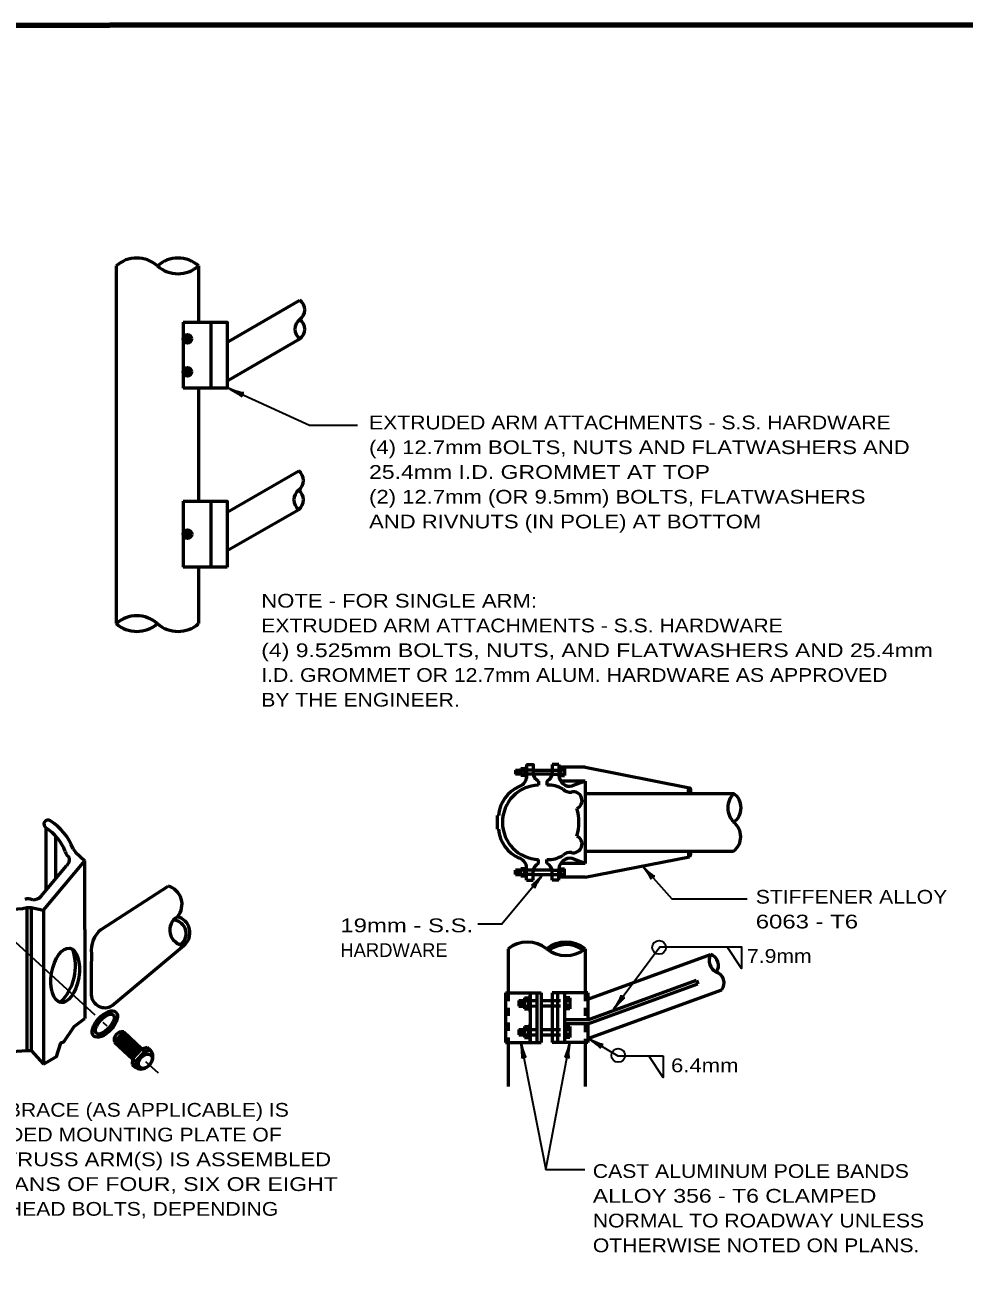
# Model space of a CAD drawing. Extents: x -20 to 693, y -19 to 435.
# Drawn here: x 342.4 to 513.2, y 202.7 to 429.4 of the extents above; entities that cross this region are included whole.
import ezdxf

# ---------------------------------------------------------------- set-up
doc = ezdxf.new("R2010")
doc.units = 0
doc.linetypes.add('SHORT_DASHED', pattern=[2.7, 1.5, -1.2])
doc.layers.add('1', color=7, linetype='Continuous', lineweight=53)

msp = doc.modelspace()

# ---------------------------------------------------------------- hatches: boundary and pattern name
at = {"layer": '1'}
for points in [[(372.737, 372.31, 1), (371.205, 372.31, 1)], [(372.737, 366.308, 1), (371.205, 366.308, 1)], [(372.741, 336.811, 1), (371.209, 336.811, 1)]]:
    msp.add_hatch(color=256, dxfattribs=at).paths.add_polyline_path(points)

# ---------------------------------------------------------------- linework, layer by layer
for p, q in [((359.012, 385.571), (359.012, 320.571)), ((374.012, 385.571), (374.012, 375.321)), ((379.415, 371.823), (392.406, 379.323)), ((371.216, 375.321), (371.216, 363.321)), ((376.216, 375.321), (376.216, 363.321)), ((379.415, 364.823), (392.406, 372.323)), ((374.012, 363.321), (374.012, 342.821)), ((379.216, 340.821), (392.206, 348.321)), ((371.216, 342.821), (371.216, 330.821)), ((376.216, 342.821), (376.216, 330.821)), ((379.216, 333.821), (392.206, 341.321)), ((379.216, 330.821), (371.216, 330.821)), ((374.012, 330.821), (374.012, 320.571)), ((433.609, 294.959), (433.609, 292.459)), ((439.532, 294.959), (438.282, 294.959)), ((438.282, 294.959), (438.282, 293.459)), ((439.532, 294.959), (439.532, 292.959)), ((431.597, 293.959), (431.597, 293.209)), ((431.597, 293.959), (433.347, 293.959)), ((433.347, 293.209), (431.597, 293.209)), ((431.847, 293.834), (431.847, 293.334)), ((432.097, 293.709), (432.097, 293.459)), ((432.347, 293.834), (432.347, 293.334)), ((432.597, 294.209), (432.597, 292.959)), ((432.597, 294.209), (433.347, 294.209)), ((433.347, 292.959), (432.597, 292.959)), ((433.347, 294.334), (433.597, 294.334)), ((433.347, 294.334), (433.347, 292.834)), ((433.597, 292.834), (433.347, 292.834)), ((434.859, 293.959), (438.282, 293.959)), ((438.271, 293.209), (434.859, 293.209)), ((444.282, 294.459), (439.532, 294.459)), ((439.782, 294.334), (439.532, 294.334)), ((439.532, 292.834), (439.782, 292.834)), ((439.782, 294.334), (439.782, 292.834)), ((440.532, 294.209), (439.782, 294.209)), ((440.532, 293.959), (439.782, 293.959)), ((439.782, 293.209), (440.532, 293.209)), ((439.782, 292.959), (440.532, 292.959)), ((440.532, 294.209), (440.532, 292.959)), ((444.282, 294.459), (463.282, 290.709)), ((435.833, 291.959), (435.833, 291.209)), ((437.308, 291.959), (437.308, 291.209)), ((444.282, 291.959), (439.808, 291.959)), ((444.282, 291.959), (441.948, 291.063)), ((444.282, 291.959), (444.282, 276.959)), ((444.282, 289.709), (471.375, 289.709)), ((428.282, 285.709), (428.282, 283.209)), ((428.282, 285.709), (428.532, 285.709)), ((346.245, 283.45), (346.245, 272.035)), ((347.995, 281.992), (347.995, 274.135)), ((428.282, 283.209), (428.532, 283.209)), ((444.282, 279.209), (471.282, 279.209)), ((345.391, 271.009), (350.01, 276.552)), ((345.786, 268.483), (353.286, 277.483)), ((353.286, 264.983), (353.286, 277.483)), ((435.833, 276.959), (435.833, 277.709)), ((437.308, 276.959), (437.308, 277.709)), ((444.282, 276.959), (439.808, 276.959)), ((444.282, 276.959), (441.948, 277.855)), ((444.282, 274.459), (463.282, 278.209)), ((431.597, 274.995), (431.597, 275.745)), ((433.347, 275.745), (431.597, 275.745)), ((431.597, 274.995), (433.347, 274.995)), ((431.847, 275.12), (431.847, 275.62)), ((432.097, 275.245), (432.097, 275.495)), ((432.347, 275.12), (432.347, 275.62)), ((432.597, 274.745), (432.597, 275.995)), ((433.347, 275.995), (432.597, 275.995)), ((432.597, 274.745), (433.347, 274.745)), ((433.597, 276.12), (433.347, 276.12)), ((433.347, 274.62), (433.347, 276.12)), ((433.347, 274.62), (433.597, 274.62)), ((433.609, 273.959), (433.609, 276.459)), ((438.271, 275.745), (434.859, 275.745)), ((434.859, 273.959), (434.859, 275.459)), ((434.859, 274.995), (438.282, 274.995)), ((438.282, 273.959), (438.282, 275.459)), ((439.532, 276.12), (439.782, 276.12)), ((439.532, 273.959), (439.532, 275.959)), ((439.782, 274.62), (439.532, 274.62)), ((444.282, 274.459), (439.532, 274.459)), ((439.782, 274.62), (439.782, 276.12)), ((439.782, 275.995), (440.532, 275.995)), ((439.782, 275.745), (440.532, 275.745)), ((440.532, 274.995), (439.782, 274.995)), ((440.532, 274.745), (439.782, 274.745)), ((440.532, 274.745), (440.532, 275.995)), ((356.286, 264.983), (368.447, 272.88)), ((433.609, 273.959), (434.859, 273.959)), ((439.532, 273.959), (438.282, 273.959)), ((342.786, 268.983), (342.786, 242.983)), ((343.536, 268.983), (343.536, 242.983)), ((345.786, 268.483), (345.786, 240.483)), ((358.286, 251.154), (371.309, 262.081)), ((430.282, 261.459), (430.282, 253.459)), ((444.282, 261.459), (444.282, 253.459)), ((444.782, 252.308), (467.077, 260.423)), ((444.782, 248.584), (464.516, 255.766)), ((444.782, 247.834), (464.757, 255.104)), ((444.782, 245.173), (469.13, 254.035)), ((464.516, 255.766), (464.757, 255.104)), ((429.782, 253.459), (436.282, 253.459)), ((429.782, 253.459), (429.782, 244.459)), ((432.256, 252.073), (434.006, 252.073)), ((432.256, 252.073), (432.256, 251.073)), ((432.506, 251.948), (432.506, 251.198)), ((432.756, 251.823), (432.756, 251.323)), ((433.006, 251.948), (433.006, 251.198)), ((433.256, 252.573), (433.256, 250.573)), ((433.256, 252.573), (434.006, 252.573)), ((434.006, 252.823), (434.006, 250.323)), ((434.006, 252.823), (434.256, 252.823)), ((434.282, 253.459), (434.282, 244.459)), ((435.532, 253.459), (435.532, 244.459)), ((436.282, 253.459), (436.282, 244.459)), ((436.282, 252.077), (438.282, 252.08)), ((444.782, 253.459), (438.282, 253.459)), ((438.282, 253.459), (438.282, 244.459)), ((439.282, 253.459), (439.282, 244.459)), ((440.532, 253.459), (440.532, 244.459)), ((440.782, 252.834), (440.532, 252.834)), ((440.782, 252.834), (440.782, 250.334)), ((441.532, 252.584), (440.782, 252.584)), ((441.532, 252.084), (440.782, 252.084)), ((441.532, 252.584), (441.532, 250.584)), ((444.782, 253.459), (444.782, 248.584)), ((432.256, 251.073), (434.006, 251.073)), ((433.256, 250.573), (434.006, 250.573)), ((434.006, 250.323), (434.256, 250.323)), ((436.282, 251.077), (438.282, 251.08)), ((440.782, 250.334), (440.532, 250.334)), ((441.532, 251.084), (440.782, 251.084)), ((441.532, 250.584), (440.782, 250.584)), ((433.256, 247.323), (433.256, 245.323)), ((433.256, 247.323), (434.006, 247.323)), ((434.006, 247.573), (434.006, 245.073)), ((434.006, 247.573), (434.256, 247.573)), ((444.782, 248.584), (440.532, 248.584)), ((444.782, 247.834), (440.532, 247.834)), ((440.782, 247.584), (440.532, 247.584)), ((440.782, 247.584), (440.782, 245.084)), ((441.532, 247.334), (440.782, 247.334)), ((441.532, 247.334), (441.532, 245.334)), ((444.782, 247.834), (444.782, 244.459)), ((358.687, 244.509), (360.376, 246.352)), ((359.055, 244.171), (360.744, 246.014)), ((359.424, 243.833), (361.113, 245.677)), ((359.793, 243.496), (361.482, 245.339)), ((360.161, 243.158), (361.85, 245.001)), ((360.376, 246.352), (363.693, 243.312)), ((432.256, 246.823), (434.006, 246.823)), ((432.256, 246.823), (432.256, 245.823)), ((432.256, 245.823), (434.006, 245.823)), ((432.506, 246.698), (432.506, 245.948)), ((432.756, 246.573), (432.756, 246.073)), ((433.006, 246.698), (433.006, 245.948)), ((433.256, 245.323), (434.006, 245.323)), ((434.006, 245.073), (434.256, 245.073)), ((436.282, 246.827), (438.282, 246.83)), ((436.282, 245.827), (438.282, 245.83)), ((440.782, 245.084), (440.532, 245.084)), ((441.532, 246.834), (440.782, 246.834)), ((441.532, 245.834), (440.782, 245.834)), ((441.532, 245.334), (440.782, 245.334)), ((358.687, 244.509), (362.005, 241.469)), ((360.53, 242.82), (362.219, 244.663)), ((360.899, 242.482), (362.587, 244.326)), ((361.267, 242.144), (362.956, 243.988)), ((361.636, 241.807), (363.325, 243.65)), ((362.005, 241.469), (363.693, 243.312)), ((362.558, 240.962), (364.246, 242.805)), ((363.693, 243.312), (364.65, 243.605)), ((363.693, 243.312), (364.246, 242.805)), ((364.246, 242.805), (365.203, 243.098)), ((364.65, 243.605), (365.203, 243.098)), ((429.782, 244.459), (436.282, 244.459)), ((430.282, 244.459), (430.282, 236.459)), ((444.782, 244.459), (438.282, 244.459)), ((444.282, 244.459), (444.282, 236.459)), ((362.005, 241.469), (361.917, 240.473)), ((361.917, 240.473), (362.47, 239.966)), ((362.005, 241.469), (362.558, 240.962)), ((362.558, 240.962), (362.47, 239.966))]:
    msp.add_line(p, q, dxfattribs=at)
at = {"layer": '1', "linetype": 'SHORT_DASHED'}
for p, q in [((434.859, 293.959), (433.609, 293.959)), ((434.859, 293.209), (433.609, 293.209)), ((438.271, 293.209), (439.532, 293.209)), ((438.282, 293.959), (439.532, 293.959)), ((434.859, 275.745), (433.609, 275.745)), ((434.859, 274.995), (433.609, 274.995)), ((438.271, 275.745), (439.532, 275.745)), ((438.282, 274.995), (439.532, 274.995)), ((430.282, 253.459), (430.282, 244.459)), ((434.282, 252.074), (436.282, 252.077)), ((438.282, 252.08), (440.532, 252.083)), ((444.282, 253.459), (444.282, 248.584)), ((434.282, 251.074), (436.282, 251.077)), ((438.282, 251.08), (440.532, 251.083)), ((444.282, 247.834), (444.282, 244.459)), ((434.282, 246.824), (436.282, 246.827)), ((434.282, 245.824), (436.282, 245.827)), ((438.282, 246.83), (440.532, 246.833)), ((438.282, 245.83), (440.532, 245.833))]:
    msp.add_line(p, q, dxfattribs=at)
at = {"layer": '1', "lineweight": 13}
for p, q in [((463.282, 289.709), (463.282, 290.709)), ((463.282, 279.209), (463.282, 278.209))]:
    msp.add_line(p, q, dxfattribs=at)
at = {"layer": '1', "lineweight": 35}
for p, q in [((338.443, 264.755), (355.108, 249.484)), ((356.582, 248.133), (357.32, 247.457)), ((364.36, 241.006), (366.65, 238.908)), ((437.152, 221.37), (444.256, 221.37))]:
    msp.add_line(p, q, dxfattribs=at)
at = {"layer": '1', "lineweight": 158}
msp.add_lwpolyline([(687.723, 429.353), (27.973, 429.27), (28.056, -9.063)], dxfattribs=at)
at = {"layer": '1'}
for points in [[(371.216, 375.321), (379.216, 375.321), (379.216, 363.321), (371.216, 363.321)], [(371.216, 342.821), (379.216, 342.821), (379.216, 330.821)], [(433.609, 294.959), (434.859, 294.959), (434.859, 293.459)], [(351.165, 279.662), (351.592, 279.046), (353.286, 277.483)], [(342.786, 268.983), (343.536, 268.983), (345.786, 268.483)], [(353.286, 264.983), (353.286, 251.154), (353.286, 248.82)], [(345.786, 240.483), (348.176, 241.896), (348.953, 244.363), (349.516, 244.551), (351.366, 247.34), (353.286, 248.82)], [(336.286, 243.483), (338.15, 243.747), (340.026, 242.808), (342.786, 242.983)], [(342.786, 242.983), (343.536, 242.983), (345.786, 240.483)]]:
    msp.add_lwpolyline(points, dxfattribs=at)
at = {"layer": '1', "lineweight": 35}
for points in [[(379.455, 363.321), (394.175, 356.611), (402.898, 356.611)], [(454.713, 276.517), (460.039, 270.524), (473.766, 270.524)], [(436.645, 274.995), (429.131, 265.931), (424.763, 265.931)], [(449.458, 250.485), (457.844, 261.828), (472.693, 261.828), (472.693, 257.907), (470.118, 261.828)], [(444.861, 245.202), (450.225, 242.007), (458.457, 242.007)], [(432.615, 244.459), (437.152, 221.37), (441.492, 244.459)], [(458.457, 242.007), (458.457, 238.086), (455.881, 242.007)]]:
    msp.add_lwpolyline(points, dxfattribs=at)
at = {"layer": '1'}
for centre in [(371.971, 372.31), (371.971, 366.308), (371.975, 336.811)]:
    msp.add_circle(centre, 0.766, dxfattribs=at)
at = {"layer": '1', "lineweight": 35}
for centre in [(457.732, 261.716), (450.318, 242.101)]:
    msp.add_circle(centre, 1.25, dxfattribs=at)
at = {"layer": '1'}
for centre, radius, start, end in [((362.762, 381.362), 5.637, 48.29895, 131.70105), ((370.262, 381.362), 5.637, 48.29895, 131.70105), ((370.262, 389.779), 5.637, 228.29895, 311.70105), ((391.116, 377.573), 2.174, 306.3891, 53.6109), ((393.685, 374.073), 2.174, 126.3891, 233.6109), ((391.116, 374.073), 2.174, 306.3891, 53.6109), ((390.916, 346.571), 2.174, 306.3891, 53.6109), ((393.485, 343.071), 2.174, 126.3891, 233.6109), ((390.916, 343.071), 2.174, 306.3891, 53.6109), ((362.762, 316.363), 5.637, 48.29895, 131.70105), ((362.762, 324.78), 5.637, 228.29895, 311.70105), ((370.262, 324.78), 5.637, 228.29895, 311.70105), ((431.589, 292.908), 2.069, 289.57732, 347.45502), ((436.415, 293.403), 1.557, 177.95818, 248.04926), ((436.726, 293.403), 1.557, 291.95074, 2.04182), ((441.484, 292.959), 1.952, 180.00917, 283.74588), ((434.754, 285.229), 6.24, 113.33464, 175.59), ((435.999, 284.459), 6.752, 91.40761, 268.59239), ((437.643, 286.266), 4.954, 57.81212, 93.88207), ((441.541, 291.736), 1.794, 225.41014, 277.71996), ((442.139, 288.411), 1.588, 293.87794, 102.99195), ((473.788, 287.084), 3.566, 132.59281, 227.40719), ((469.441, 287.084), 3.207, 305.05336, 54.94663), ((434.722, 284.459), 8.439, 342.76732, 17.23267), ((341.55, 276.036), 8.775, 20.66388, 57.65371), ((341.55, 276.036), 10.275, 20.66388, 57.65371), ((469.286, 281.834), 3.298, 307.2562, 52.7438), ((434.754, 283.688), 6.24, 184.41, 246.66536), ((442.139, 280.506), 1.588, 257.00805, 66.12206), ((351.362, 279.499), 1.642, 192.85463, 230.60442), ((441.541, 277.181), 1.794, 82.28004, 134.58986), ((348.39, 278.041), 2.201, 317.4286, 347.16534), ((349.7, 277.66), 0.842, 352.66912, 42.58165), ((431.589, 276.009), 2.069, 12.54498, 70.42267), ((436.415, 275.514), 1.557, 111.95074, 182.04182), ((437.643, 282.651), 4.954, 266.11793, 302.18787), ((436.726, 275.514), 1.557, 357.95818, 68.04926), ((441.484, 275.958), 1.952, 76.25412, 179.99082), ((367.528, 269.545), 3.459, 319.44782, 74.5999), ((343.033, 268.914), 1.642, 62.80268, 111.90546), ((343.851, 272.557), 2.183, 268.23866, 314.85412), ((340.283, 278.949), 10.275, 247.10638, 284.09621), ((371.561, 264.872), 2.802, 120.08888, 264.83066), ((369.24, 264.241), 2.482, 304.09123, 82.55014), ((369.451, 264.406), 2.975, 308.63104, 76.2885), ((359.282, 261.238), 4.796, 128.66194, 187.87931), ((342.384, 258.325), 9.229, 314.33212, 19.09649), ((433.782, 257.098), 5.591, 51.2455, 128.7545), ((440.782, 257.098), 5.591, 51.2455, 128.7545), ((440.782, 265.819), 5.591, 231.2455, 308.7545), ((440.847, 257.04), 5.191, 53.42334, 127.51258), ((473.137, 256.082), 118.691, 177.82775, 181.44113), ((469.296, 259.374), 2.454, 154.68436, 240.93436), ((466.528, 258.485), 2.015, 321.44112, 74.17759), ((467.554, 255.291), 2.015, 321.44112, 74.17759), ((356.955, 253.242), 2.476, 183.35172, 302.5103), ((360.104, 244.906), 1.472, 79.351, 195.65274), ((363.782, 241.82), 1.911, 319.45702, 41.96074), ((363.516, 241.335), 1.722, 232.63043, 305.57785)]:
    msp.add_arc(centre, radius, start, end, dxfattribs=at)
at = {"layer": '1', "lineweight": 40}
for centre, major_axis, ratio, start_param, end_param in [((380.387, 362.664), (1.525, -0.888), 0.07063, 6.2823074, 8.5597026), ((380.387, 362.664), (1.525, -0.888), 0.07063, 6.2823074, 8.5597026), ((380.563, 363.12), (-1.69, 0.599), 0.122415, 0.8963533, 3.1415927), ((380.563, 363.12), (-1.69, 0.599), 0.122415, 0.8963533, 3.1415927), ((455.3, 275.539), (-1.035, 1.43), 0.07063, 3.1407148, 5.41811), ((455.3, 275.539), (-1.035, 1.43), 0.07063, 3.1407148, 5.41811), ((455.645, 275.885), (-1.303, 1.231), 0.122415, 0.8963533, 3.1415927), ((455.645, 275.885), (-1.303, 1.231), 0.122415, 0.8963533, 3.1415927), ((435.767, 274.267), (-1.256, -1.24), 0.07063, 6.2823074, 8.5597026), ((435.767, 274.267), (-1.256, -1.24), 0.07063, 6.2823074, 8.5597026), ((436.161, 273.978), (1.019, 1.474), 0.122415, 0.8963533, 3.1415927), ((436.161, 273.978), (1.019, 1.474), 0.122415, 0.8963533, 3.1415927), ((449.884, 251.527), (-0.936, -1.529), 0.122415, 0.8963533, 3.1415927), ((450.294, 251.261), (-1.185, -1.308), 0.07063, 3.1407148, 5.41811), ((445.715, 244.447), (-1.419, 1.05), 0.07063, 3.1407148, 5.41811), ((445.715, 244.447), (-1.419, 1.05), 0.07063, 3.1407148, 5.41811), ((445.94, 244.881), (-1.614, 0.779), 0.122415, 0.8963533, 3.1415927), ((445.94, 244.881), (-1.614, 0.779), 0.122415, 0.8963533, 3.1415927), ((432.623, 243.318), (-0.166, 1.757), 0.07063, 3.1407148, 5.41811), ((433.096, 243.441), (-0.498, 1.722), 0.122415, 0.8963533, 3.1415927), ((441.077, 243.397), (-0.497, -1.694), 0.07063, 6.2823074, 8.5597026), ((441.077, 243.397), (-0.497, -1.694), 0.07063, 6.2823074, 8.5597026), ((441.562, 243.335), (0.176, 1.784), 0.122415, 0.8963533, 3.1415927), ((441.562, 243.335), (0.176, 1.784), 0.122415, 0.8963533, 3.1415927)]:
    msp.add_ellipse(centre, major_axis=major_axis, ratio=ratio, start_param=start_param, end_param=end_param, dxfattribs=at)
at = {"layer": '1'}
for centre, major_axis, ratio in [((463.282, 290.209), (0, -0.5), 0.384798), ((463.282, 278.709), (0, -0.5), 0.333019), ((349.738, 256.639), (-0.823, -4.932), 0.5), ((356.951, 247.795), (2.002, 2.185), 0.506099), ((356.951, 247.795), (1.539, 1.679), 0.438981), ((364.324, 241.039), (1.013, 1.106), 0.666666)]:
    msp.add_ellipse(centre, major_axis=major_axis, ratio=ratio, dxfattribs=at)
msp.add_ellipse((346.647, 284.084), major_axis=(-0.671, 0.425), ratio=0.94369, start_param=4.712389, end_param=7.8539816, dxfattribs=at)

# ---------------------------------------------------------------- texts
for s, width, p in [('EXTRUDED ARM ATTACHMENTS - S.S. HARDWARE', 1.15, (404.998, 355.862)), ('(4) 12.7mm BOLTS, NUTS AND FLATWASHERS AND', 1.2, (404.998, 351.362)), ('25.4mm I.D. GROMMET AT TOP', 1.25, (404.998, 346.862)), ('(2) 12.7mm (OR 9.5mm) BOLTS, FLATWASHERS', 1.2, (404.998, 342.362)), ('AND RIVNUTS (IN POLE) AT BOTTOM', 1.2, (404.998, 337.862)), ('NOTE - FOR SINGLE ARM:', 1.2, (385.396, 323.473)), ('EXTRUDED ARM ATTACHMENTS - S.S. HARDWARE', 1.15, (385.396, 318.973)), ('(4) 9.525mm BOLTS, NUTS, AND FLATWASHERS AND 25.4mm', 1.25, (385.396, 314.473)), ('I.D. GROMMET OR 12.7mm ALUM. HARDWARE AS APPROVED', 1.15, (385.396, 309.973)), ('BY THE ENGINEER.', 1.15, (385.396, 305.473)), ('STIFFENER ALLOY', 1.15, (475.316, 269.669)), ('6063 - T6', 1.3, (475.316, 265.169)), ('19mm - S.S.', 1.3, (399.779, 264.478)), ('7.9mm', 1.15, (473.724, 258.919)), ('6.4mm', 1.2, (459.906, 239.037)), ('MAIN ARM AND UNDERBRACE (AS APPLICABLE) IS', 1.15, (295.986, 230.956)), ('WELDED TO AN EXTRUDED MOUNTING PLATE OF', 1.15, (295.986, 226.456)), ('ALLOY 6061 - T6. THE TRUSS ARM(S) IS ASSEMBLED', 1.2, (295.986, 221.956)), ('CAST ALUMINUM POLE BANDS', 1.15, (445.687, 219.832)), ('TO THE SHAFT BY MEANS OF FOUR, SIX OR EIGHT', 1.25, (295.986, 217.456)), ('ALLOY 356 - T6 CLAMPED', 1.25, (445.687, 215.332)), ('RIVNUTS OR S.S. HEX. HEAD BOLTS, DEPENDING', 1.15, (295.986, 212.956)), ('NORMAL TO ROADWAY UNLESS', 1.15, (445.687, 210.832)), ('OTHERWISE NOTED ON PLANS.', 1.15, (445.687, 206.332))]:
    msp.add_text(s, height=2.5, dxfattribs=dict(at, width=width)).set_placement(p)
msp.add_text('HARDWARE', height=2.5, dxfattribs=at).set_placement((399.779, 259.978))

doc.saveas('drawing.dxf')
